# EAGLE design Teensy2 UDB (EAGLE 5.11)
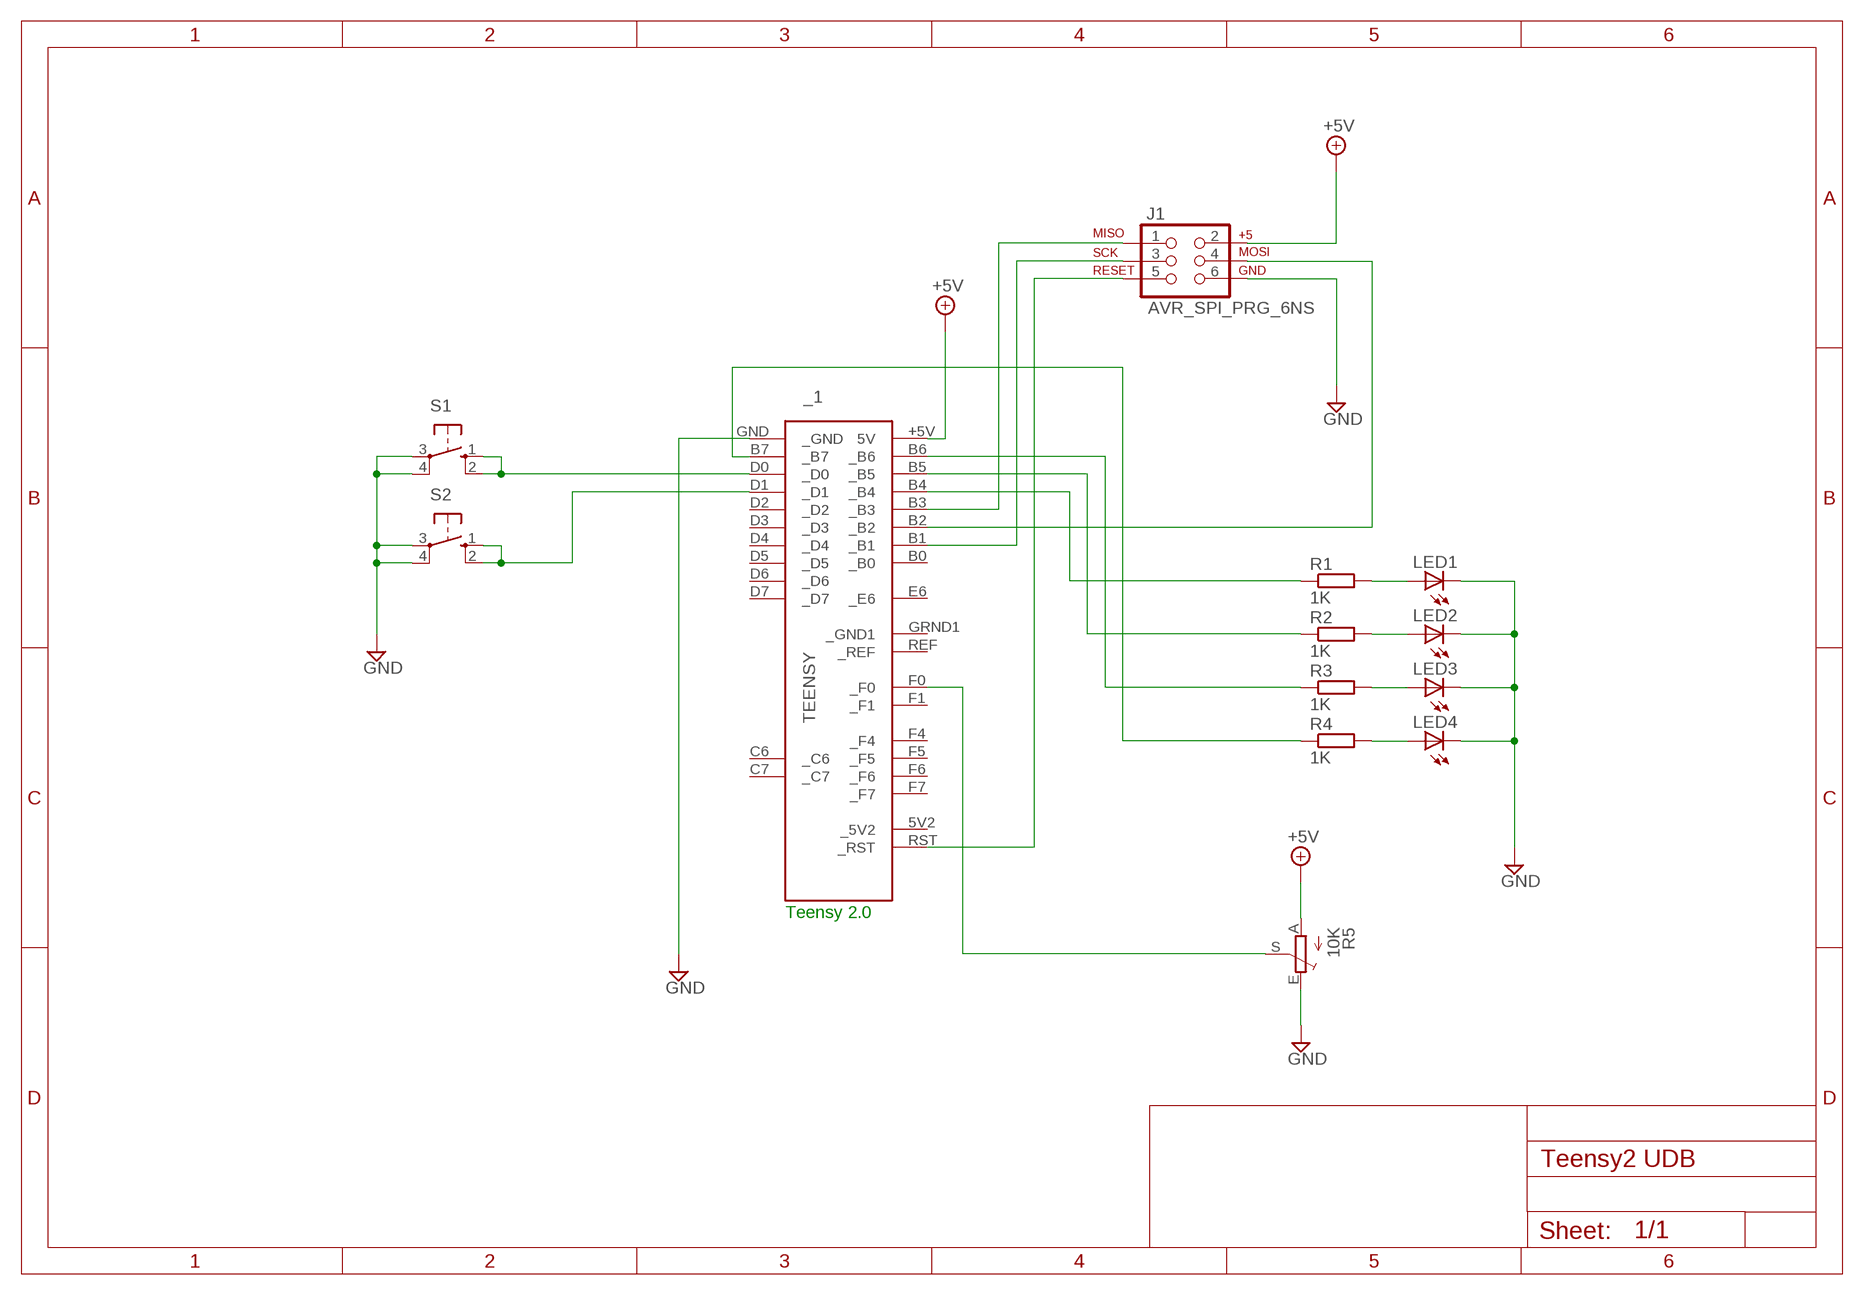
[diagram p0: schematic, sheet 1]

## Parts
_1  TEENSY  [TEENSY]
J1  AVR_SPI_PRG_6NS  [2X3-NS]
LED1  LED5MM  [LED5MM]
LED2  LED5MM  [LED5MM]
LED3  LED5MM  [LED5MM]
LED4  LED5MM  [LED5MM]
R1  1K  R-EU_0207/10  [0207/10]
R2  1K  R-EU_0207/10  [0207/10]
R3  1K  R-EU_0207/10  [0207/10]
R4  1K  R-EU_0207/10  [0207/10]
R5  10K  TRIM_EU-CA9V  [CA9V]
S1  10-XX  [B3F-10XX]
S2  10-XX  [B3F-10XX]

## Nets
+5V: _1.+5V(5V) J1.2 R5.A
GND: _1.GND(_GND) J1.6 LED1.K(C) LED2.K(C) LED3.K(C) LED4.K(C) R5.E S1.3(P) S1.4(P1) S2.3(P) S2.4(P1)
N$1: _1.B3(_B3) J1.1
N$2: _1.B1(_B1) J1.3
N$3: _1.RST(_RST) J1.5
N$4: LED4.A R4.2
N$5: _1.B4(_B4) R1.1
N$6: _1.B5(_B5) R2.1
N$7: _1.B6(_B6) R3.1
N$8: _1.B2(_B2) J1.4
N$10: LED1.A R1.2
N$11: LED2.A R2.2
N$12: LED3.A R3.2
N$13: _1.B7(_B7) R4.1
N$14: _1.D0(_D0) S1.1(S) S1.2(S1)
N$15: _1.D1(_D1) S2.1(S) S2.2(S1)
N$17: _1.F0(_F0) R5.S
Unconnected: _1.5V2(_5V2) _1.B0(_B0) _1.C6(_C6) _1.C7(_C7) _1.D2(_D2) _1.D3(_D3) _1.D4(_D4) _1.D5(_D5) _1.D6(_D6) _1.D7(_D7) _1.E6(_E6) _1.F1(_F1) _1.F4(_F4) _1.F5(_F5) _1.F6(_F6) _1.F7(_F7) _1.GRND1(_GND1) _1.REF(_REF)

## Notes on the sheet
- Teensy 2.0

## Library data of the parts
_1 = teensy:TEENSY: Teensy 2.0
J1 = SparkFun:AVR_SPI_PRG_6: AVR ISP 6 Pin This is the reduced ISP connector for AVR programming. Common on Arduino. This footprint will take up less PCB space and can be used with a 10-pin to 6-pin adapter such as SKU: BOB-08508
LED1-LED4 = SparkFun:LED: LEDs
R1-R4 = resistor:R-EU_: RESISTOR, European symbol
R5 = pot:TRIM_EU-: POTENTIOMETER
S1 S2 = switch-omron:10-XX: OMRON SWITCH; MPN: B3F-1000; OC_FARNELL: 176432; OC_NEWARK: 36M3542

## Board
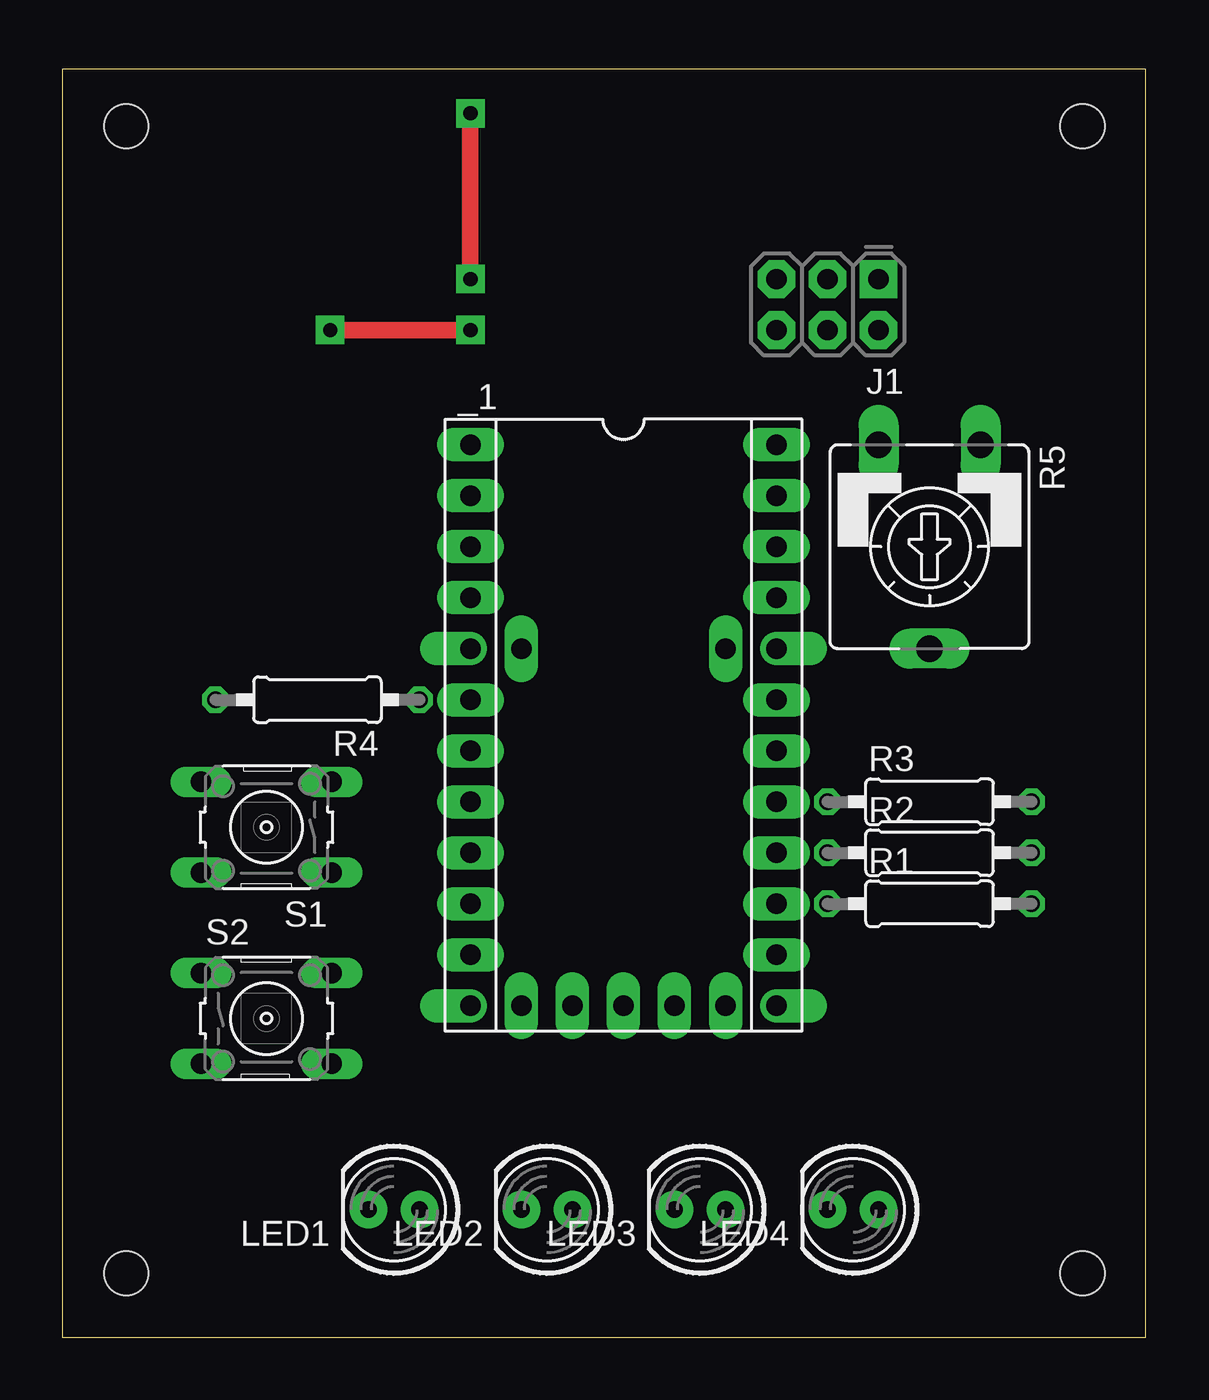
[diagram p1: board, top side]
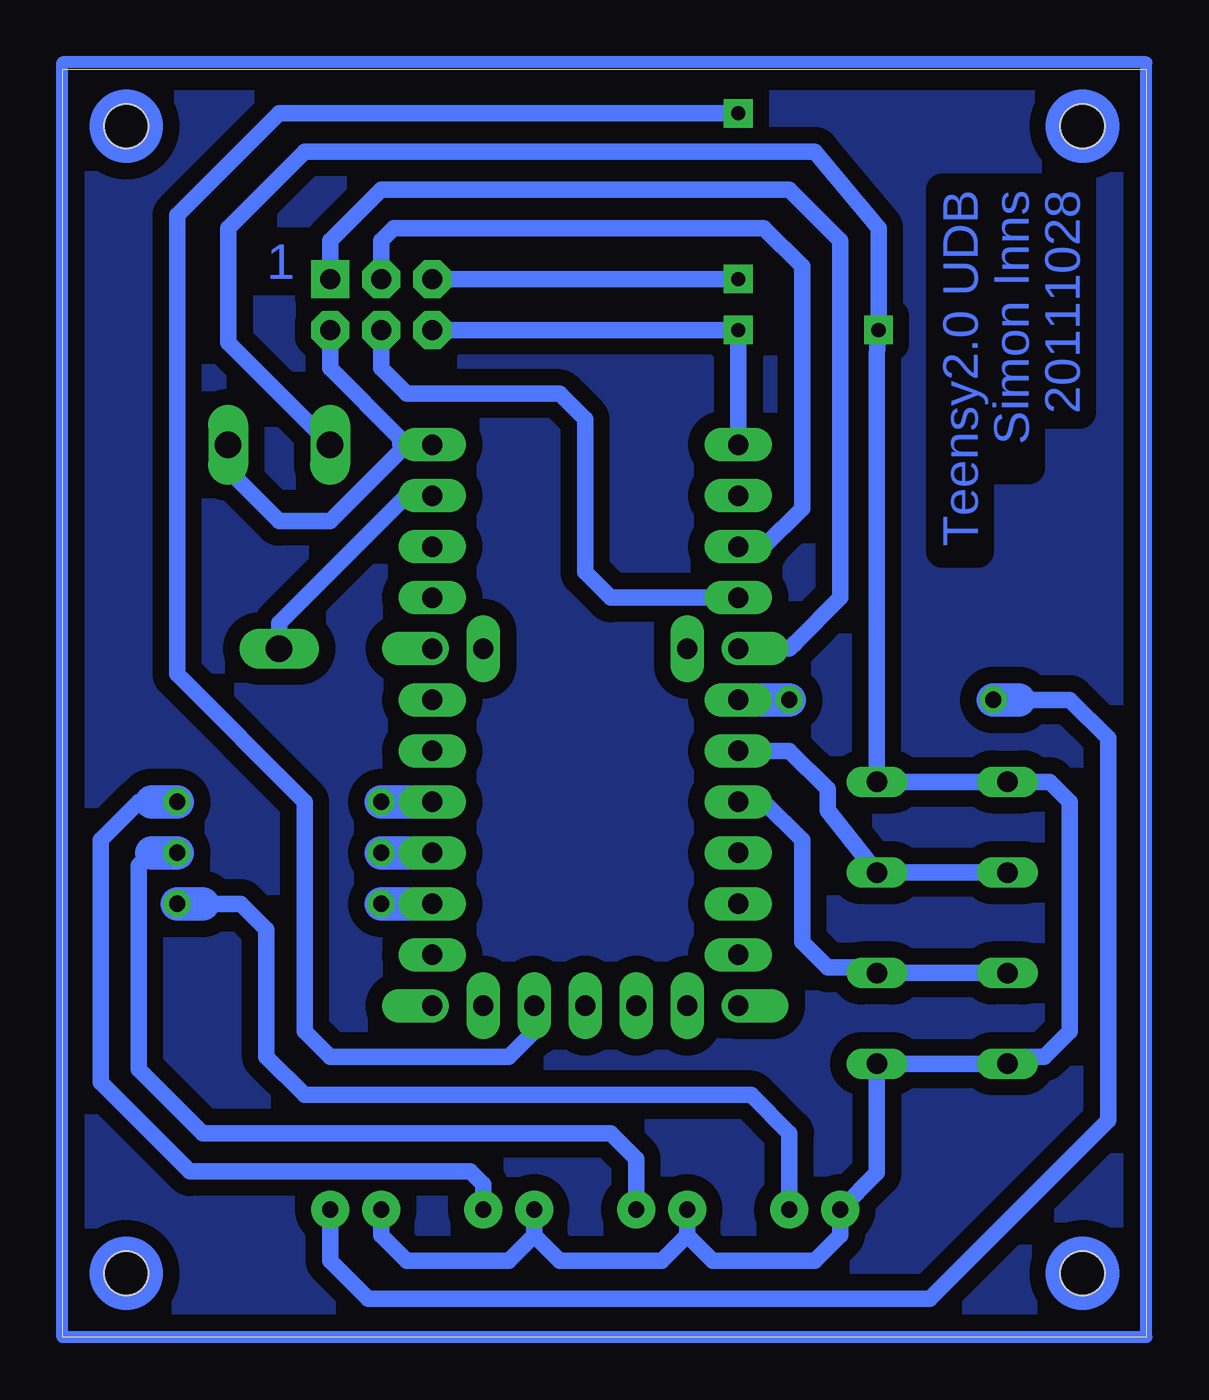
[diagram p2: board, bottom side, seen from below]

Size 53.95 x 63.17 mm. Coordinates in mm from the lower left corner, seen from the top.
Outline: 0,0 53.95,0 53.95,63.17 0,63.17 0,0
Copper layers (1*16): Top 0.035mm / dielectric 1.5mm / Bottom 0.035mm
Design rules "default": minimum track width 10mil, minimum drill 24mil, track to track 8mil, track to pad 8mil, pad to pad 8mil, via to via 8mil, smd to smd 8mil, copper to edge 40mil, drill to drill 8mil, minimum pad ring 10mil, minimum via ring 8mil, stop-mask expansion 4mil, vias tented up to drill 0mil, thermal gap 10mil
Holes 2.2 mm at 3.17,60.33 50.8,60.33 50.8,3.17 3.17,3.17

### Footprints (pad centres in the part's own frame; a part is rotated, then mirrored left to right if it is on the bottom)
TEENSY = drill 1 pad 1.676 long: 5V2 13.97,-2.54; +5V -13.97,7.62; B0 -11.43,-7.62; B1 -8.89,-7.62; B2 -6.35,-7.62; B4 8.89,7.62; B5 6.35,7.62; B6 3.81,7.62; B7 -1.27,-7.62; C6 11.43,-7.62; D0 1.27,-7.62; D1 3.81,-7.62; D2 6.35,-7.62; D3 8.89,-7.62; D4 13.97,5.08; D5 13.97,-5.08; D7 11.43,7.62; E6 -3.81,-5.08; F0 -11.43,7.62; F1 -8.89,7.62; F4 -6.35,7.62; F6 -1.27,7.62; F7 1.27,7.62; GND -13.97,-7.62; GRND1 13.97,0; REF -3.81,5.08; RST 13.97,2.54 | drill 1 pad 1.676 offset: B3 -3.81,-7.62; C7 13.97,-7.62; D6 13.97,7.62; F5 -3.81,7.62
2X3-NS = drill 1.016 pad 1.88 square: 1 -2.54,-1.27 | drill 1.016 pad 1.88 octagon: 2 -2.54,1.27; 3 0,-1.27; 4 0,1.27; 5 2.54,-1.27; 6 2.54,1.27
LED5MM = drill 0.813 pad 1.88 round: A -1.27,0; K 1.27,0
0207/10 = drill 0.813 octagon: 1 -5.08,0; 2 5.08,0
CA9V = drill 1.321 long: A -2.54,-5.08; E 2.54,-5.08; S 0,5.08
B3F-10XX = drill 1.016 long: 1 -3.251,2.261; 2 3.251,2.261; 3 -3.251,-2.261; 4 3.251,-2.261

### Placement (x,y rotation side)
_1  27.94,30.48 270 top
J1  38.1,51.44 180 top
LED1  16.51,6.35 180 top
LED2  24.13,6.35 180 top
LED3  31.75,6.35 180 top
LED4  39.37,6.35 180 top
R1  43.18,21.59 0 top
R2  43.18,24.13 0 top
R3  43.18,26.67 0 top
R4  12.7,31.75 180 top
R5  43.18,39.37 180 top
S1  10.16,25.4 180 top
S2  10.16,15.88 0 top

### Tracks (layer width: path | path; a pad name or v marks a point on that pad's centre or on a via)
+5V
  Bottom 0.813: R5.A 45.72,43.18 43.18,40.64 40.64,40.64 36.83,44.45 37.15,44.77 | J1.2 40.64,48.26 37.15,44.77 | _1.+5V 37.15,44.45 37.15,44.77
GND  (via drill 0.7 pad 1.42)
  Top 0.813: v13.34,50.16 v20.32,50.16
  Bottom 0.813: S1.3 S1.4 | S1.3 4.8,27.66 3.81,26.67 3.81,15.24 5.08,13.97 5.99,13.97 S2.3 S2.4 13.41,8.18 LED1.K 15.24,5.08 16.51,3.81 21.59,3.81 22.86,5.08 | 22.86,5.08 LED2.K 22.86,5.08 | 22.86,5.08 24.13,3.81 29.21,3.81 30.48,5.08 | 30.48,5.08 LED3.K 30.48,5.08 | 30.48,5.08 31.75,3.81 36.83,3.81 38.1,5.08 LED4.K | S1.3 13.41,48.97 v13.34,50.16 13.34,55.24 16.51,59.05 30.48,59.05 39.37,59.05 41.91,59.05 45.72,55.24 45.72,49.53 R5.E | J1.6 v20.32,50.16 _1.GND
N$1
  Bottom 0.813: J1.1 40.64,54.61 38.1,57.15 17.78,57.15 15.24,54.61 15.24,53.98 15.24,36.83 17.46,34.61 17.78,34.29 _1.B3
N$2
  Bottom 0.813: J1.3 38.1,54.61 37.47,55.24 19.05,55.24 17.14,53.34 17.14,42.55 17.14,41.27 19.05,39.37 _1.B1
N$3  (via drill 0.7 pad 1.42)
  Top 0.813: v20.32,60.96 v20.32,52.7
  Bottom 0.813: v20.32,60.96 34.29,60.96 43.18,60.96 48.26,55.88 48.26,33.02 41.91,26.67 41.91,24.13 41.91,15.24 40.64,13.97 31.75,13.97 30.48,15.24 _1.RST | v20.32,52.7 J1.5
N$4
  Bottom 0.813: LED4.A 40.64,3.81 38.73,1.91 10.79,1.91 1.91,10.79 1.91,29.84 3.81,31.75 6.35,31.75
  Bottom 1.676: 6.35,31.75 R4.2
N$5
  Bottom 1.676: _1.B4 R1.1
N$6
  Bottom 1.676: _1.B5 R2.1
N$7
  Bottom 1.676: _1.B6 R3.1
N$8
  Bottom 0.813: J1.4 38.1,48.26 36.83,46.99 29.21,46.99 27.94,45.72 27.94,38.1 26.67,36.83 _1.B2
N$9
  Bottom 0.61: 0,63.5 53.98,63.5 53.98,0 0,0 0,63.5
N$10
  Bottom 0.813: LED1.A 17.78,10.16 19.68,12.06 41.91,12.06 43.81,13.97 43.81,20.32 45.09,21.59 46.99,21.59
  Bottom 1.676: 46.99,21.59 R1.2
N$11
  Bottom 0.813: LED2.A 25.4,8.89 26.67,10.16 46.99,10.16 50.16,13.34 50.16,22.23 50.16,23.5 49.53,24.13
  Bottom 1.676: 49.53,24.13 R2.2
N$12
  Bottom 0.813: LED3.A 33.02,7.62 33.66,8.26 47.62,8.26 52.07,12.7 52.07,24.13 52.07,24.77 50.16,26.67 49.53,26.67
  Bottom 1.676: 49.53,26.67 R3.2
N$13
  Bottom 1.676: R4.1 _1.B7
N$14
  Bottom 0.813: S1.2 S1.1 15.88,26.24 15.88,27.3 17.78,29.21 _1.D0
N$15
  Bottom 0.813: S2.1 S2.2 14.33,18.41 15.88,18.41 17.14,19.68 17.14,24.77 19.05,26.67 _1.D1
N$16
  pour Bottom (isolate 0.813): 0,63.5 53.98,63.5 53.98,0 0,0
N$17
  Bottom 0.813: R5.S 43.18,35.56 36.83,41.91 _1.F0
(copper drawn outside any net)
  shapes: Bottom circle x4

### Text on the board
Bottom: 20111028 | Simon Inns | Teensy2.0 UDB | 1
